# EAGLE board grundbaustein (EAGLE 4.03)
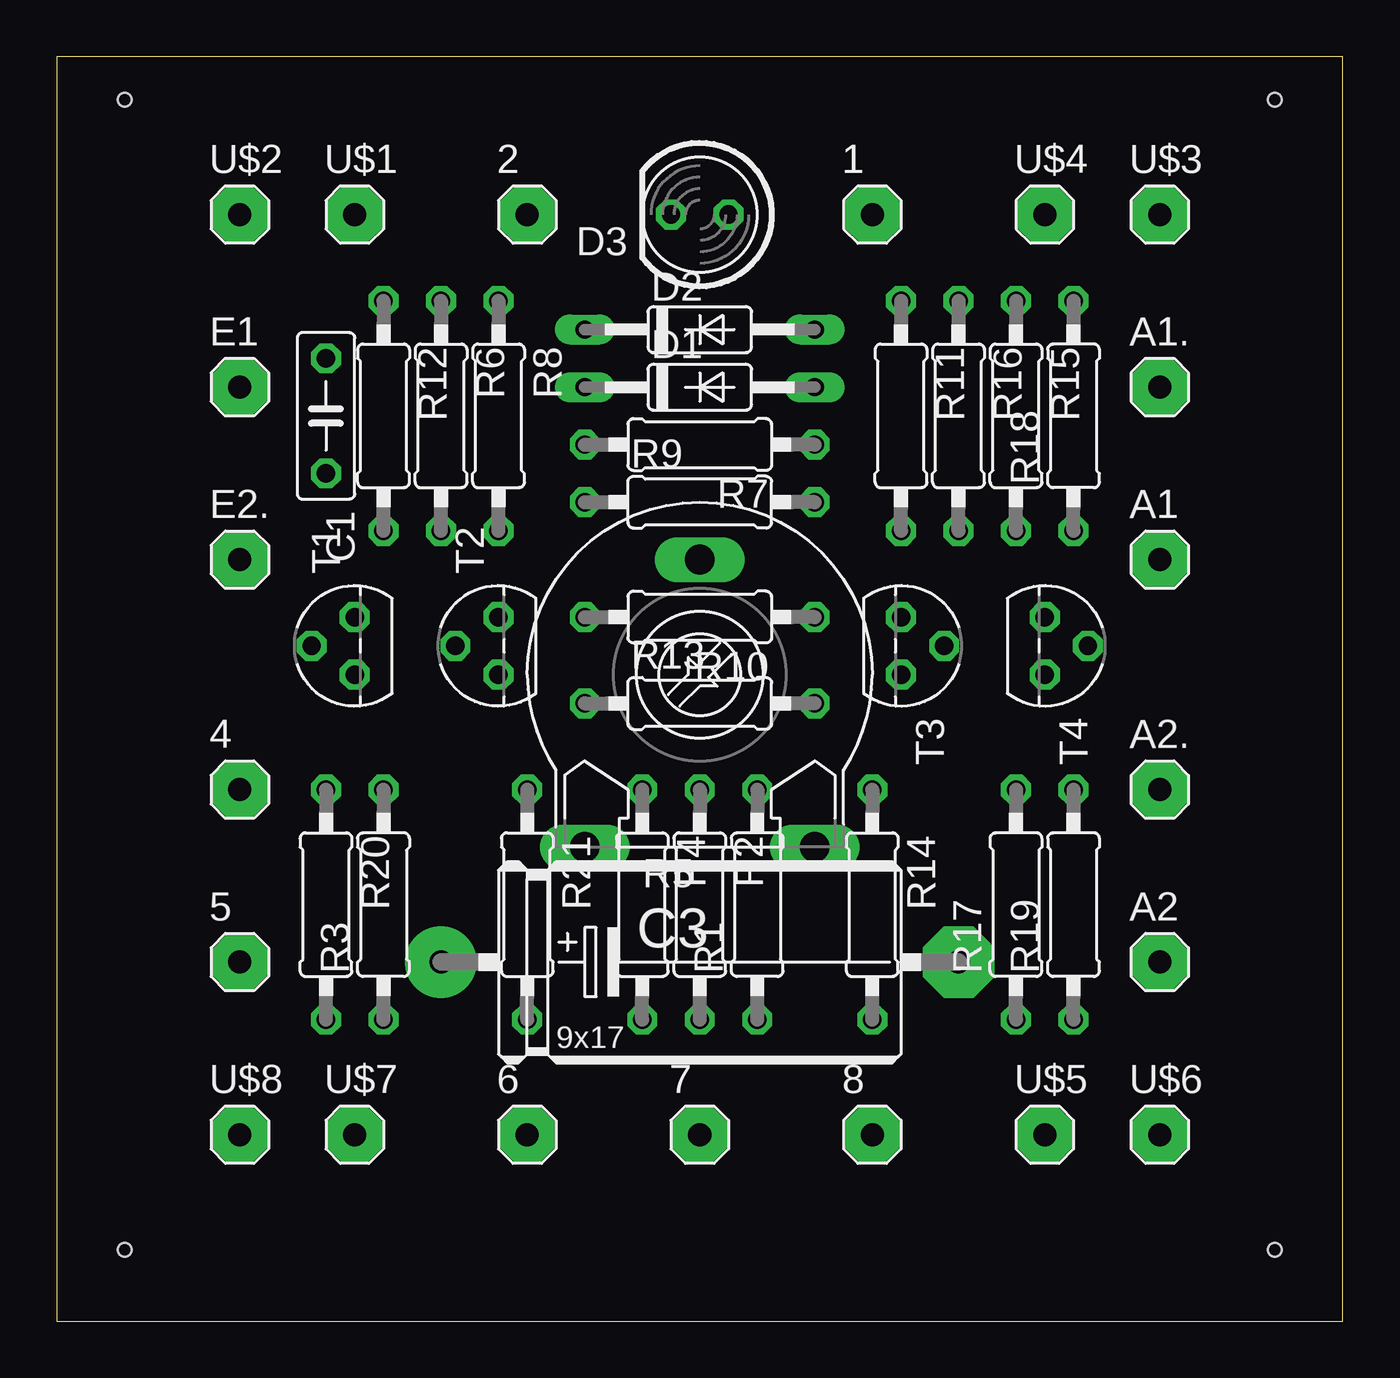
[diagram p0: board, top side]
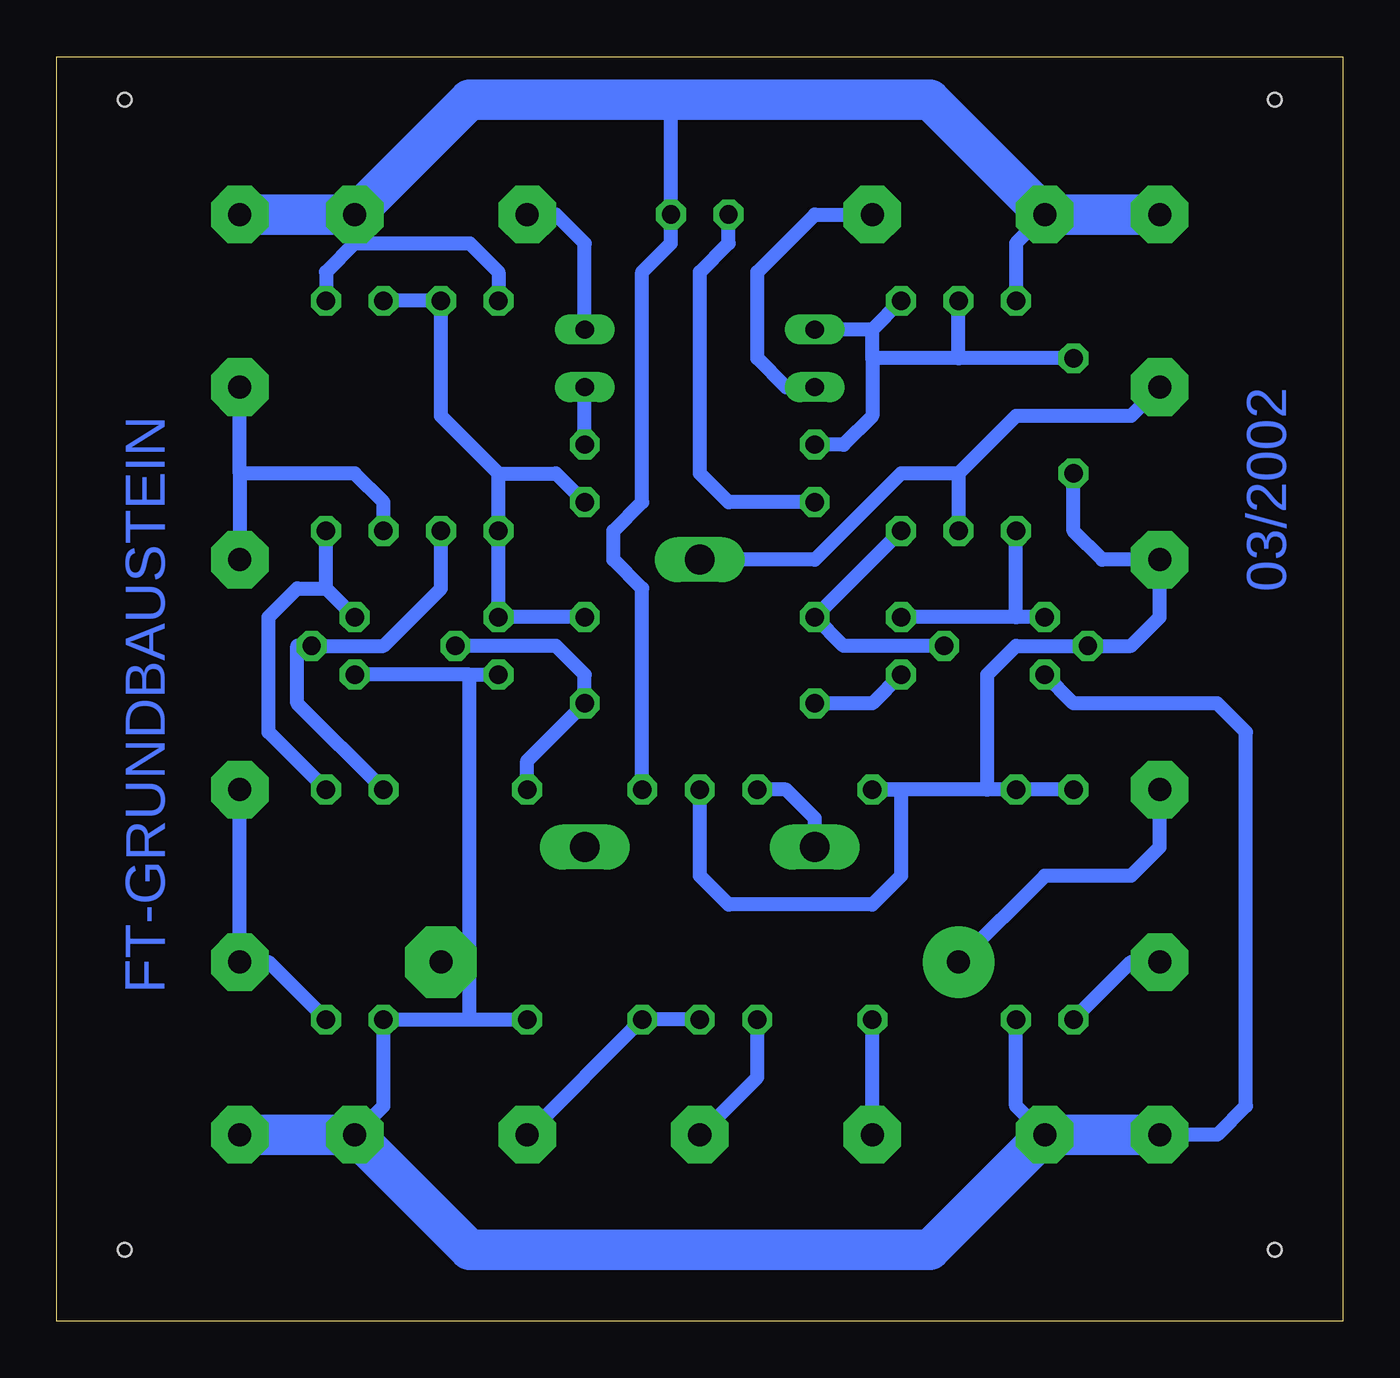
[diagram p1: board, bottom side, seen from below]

Size 56.82 x 55.87 mm. Coordinates in mm from the lower left corner, seen from the top.
Outline: 0,0 56.82,0 56.82,55.87 0,55.87 0,0
Copper layers used: Bottom
Holes 0.61 mm at 3.01,3.17 53.81,3.17 3.01,53.97 53.81,53.97

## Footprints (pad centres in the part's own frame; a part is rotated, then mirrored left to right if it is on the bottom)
1X01 = drill 1.016 pad 2.54 octagon: 1 0,0
C050-025X075 = drill 0.813 octagon: 1 -2.54,0; 2 2.54,0
E22-9 = drill 1.016 pad 3.15 round: + -11.43,0 | drill 1.016 pad 3.15 octagon: - 11.43,0
DO35-10 = drill 0.813 long: A 5.08,0; C -5.08,0
LED5MM = drill 0.813 octagon: A -1.27,0; K 1.27,0
0207/10 = drill 0.813 octagon: 1 -5.08,0; 2 5.08,0
LI15 = drill 1.321 long: 1 -5.08,-7.62; 2 0,5.08; 3 5.08,-7.62
TO92 = drill 0.813 octagon: 1 1.27,0; 2 0,1.905; 3 -1.27,0

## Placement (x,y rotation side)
1  1  [1X01]  36.03,48.89 0 top
2  2  [1X01]  20.79,48.89 0 top
4  4  [1X01]  8.09,23.49 0 top
5  PINHD-1X1-BA  [1X01]  8.09,15.87 0 top
6  PINHD-1X1-BA  [1X01]  20.79,8.25 0 top
7  7  [1X01]  28.41,8.25 0 top
8  8  [1X01]  36.03,8.25 0 top
A1  a1  [1X01]  48.73,33.65 0 top
A1.  a1  [1X01]  48.73,41.27 0 top
A2  a2  [1X01]  48.73,15.87 0 top
A2.  a2  [1X01]  48.73,23.49 0 top
C1  [C050-025X075]  11.9,40 270 top
C3  [E22-9]  28.41,15.87 0 top
D1  1N4148  [DO35-10]  28.41,41.27 0 top
D2  1N4148  [DO35-10]  28.41,43.81 0 top
D3  LED5MM  [LED5MM]  28.41,48.89 180 top
E1  e1  [1X01]  8.09,41.27 0 top
E2.  e2  [1X01]  8.09,33.65 0 top
R1  [0207/10]  30.95,18.41 90 top
R2  [0207/10]  28.41,18.41 270 top
R3  [0207/10]  14.44,18.41 90 top
R4  [0207/10]  25.87,18.41 270 top
R5  [LI15]  28.41,28.57 0 top
R6  [0207/10]  16.98,40 270 top
R7  [0207/10]  28.41,38.73 180 top
R8  [0207/10]  19.52,40 270 top
R9  [0207/10]  28.41,36.19 0 top
R10  [0207/10]  28.41,31.11 180 top
R11  [0207/10]  37.3,40 270 top
R12  [0207/10]  14.44,40 270 top
R13  [0207/10]  28.41,27.3 0 top
R14  [0207/10]  36.03,18.41 270 top
R15  [0207/10]  42.38,40 270 top
R16  [0207/10]  39.84,40 270 top
R17  [0207/10]  42.38,18.41 90 top
R18  [0207/10]  44.92,40 90 top
R19  [0207/10]  44.92,18.41 90 top
R20  [0207/10]  11.9,18.41 270 top
R21  [0207/10]  20.79,18.41 270 top
T1  BC307  [TO92]  13.17,29.84 90 top
T2  BC307  [TO92]  19.52,29.84 90 top
T3  BC238  [TO92]  37.3,29.84 270 top
T4  BC238  [TO92]  43.65,29.84 270 top
U$1  +9v  [1X01]  13.17,48.89 0 top
U$2  +9v  [1X01]  8.09,48.89 0 top
U$3  +9v  [1X01]  48.73,48.89 0 top
U$4  +9v  [1X01]  43.65,48.89 0 top
U$5  gnd  [1X01]  43.65,8.25 0 top
U$6  gnd  [1X01]  48.73,8.25 0 top
U$7  gnd  [1X01]  13.17,8.25 0 top
U$8  gnd  [1X01]  8.09,8.25 0 top

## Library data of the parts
1 2 4-8 A1 A1. A2 A2. E1 E2. U$1-U$8 = pinhead
C1 C3 R1-R4 R6-R21 = rcl
D1 D2 = diode
D3 = led
R5 = pot
T1 T2 = transistor-pnp
T3 T4 = transistor-npn

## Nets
N$1: D3.A R1.2 R11.1 R12.1 R18.2 U$1.1 U$2.1 U$3.1 U$4.1
N$2: 7.1 R4.2
N$3: 2.1 D1.C
N$4: 1.1 D2.A
N$5: 5.1 R20.2
N$6: 4.1 C3.+
N$7: 6.1 R21.2
N$9: D1.A R7.1
N$10: R4.1 R5.1
N$11: 8.1 R1.1 R2.2
N$12: D3.K R9.1
N$13: E1.1 R5.2 R6.2
N$14: R16.2 R17.2 T4.2
N$15: C1.1 D2.C R6.1 R7.2 R8.1
N$16: R9.2 R10.1 R11.2 R15.1 R16.1 T3.3
N$17: R8.2 R10.2 T2.2
N$19: C1.2 E2..1 R2.1 R3.2 R20.1 R21.1 T1.2
N$20: C3.- R3.1 R14.2 R17.1 T1.3 T3.1 T4.1 U$5.1 U$6.1 U$7.1 U$8.1
N$24: R12.2 T1.1 T2.1
N$25: R13.1 T2.3
N$26: R13.2 R14.1 T3.2
N$38: R18.1 R19.2 T4.3
N$43: A2.1 A2..1 R19.1
N$45: A1.1 A1..1 R15.2

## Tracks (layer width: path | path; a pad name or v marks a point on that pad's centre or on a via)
N$1
  Bottom 0.61: U$4.1 43.65,47.62 | 43.65,47.62 44.92,46.35 R18.2 | R11.1 37.3,46.35 38.57,47.62 43.65,47.62 | 29.68,53.97 D3.A 29.68,47.62 30.95,46.35 30.95,36.19 32.22,34.92 32.22,33.65 30.95,32.38 R1.2 | U$1.1 14.44,47.62 R12.1
  Bottom 1.778: U$2.1 U$1.1 18.25,53.97 29.68,53.97 38.57,53.97 U$4.1 U$3.1
N$2
  Bottom 0.61: R4.2 25.87,10.79 7.1
N$3
  Bottom 0.61: 2.1 23.33,48.89 25.87,46.35 25.87,42.54 24.6,41.27 D1.C
N$4
  Bottom 0.61: 1.1 34.76,48.89 33.49,47.62 D2.A
N$5
  Bottom 0.61: 5.1 9.36,15.87 R20.2
N$6
  Bottom 0.61: 4.1 8.09,20.95 9.36,19.68 13.17,19.68 C3.+
N$7
  Bottom 0.61: 6.1 R21.2
N$9
  Bottom 0.61: R7.1 D1.A
N$10
  Bottom 0.61: R4.1 24.6,23.49 23.33,22.22 R5.1
N$11
  Bottom 0.61: R2.2 R1.1 8.1
N$12
  Bottom 0.61: R9.1 27.14,36.19 28.41,37.46 28.41,46.35 27.14,47.62 D3.K
N$13
  Bottom 0.61: E1.1 9.36,40 14.44,40 16.98,37.46 | 16.98,37.46 R6.2 | R5.2 23.33,33.65 19.52,37.46 16.98,37.46
N$14
  Bottom 0.61: R16.2 39.84,32.38 42.38,29.84 T4.2 46.19,29.84 46.19,27.3 R17.2
N$15
  Bottom 0.61: R7.2 22.06,38.73 20.79,40 20.79,42.54 | 20.79,42.54 20.79,43.81 | 20.79,43.81 D2.C | C1.1 16.98,42.54 | 16.98,42.54 20.79,42.54 | 16.98,42.54 R6.1 | 20.79,43.81 R8.1
N$16
  Bottom 0.61: 37.3,37.46 R11.2 T3.3 R10.1 | 37.3,37.46 39.84,40 R16.1 R15.1 | 37.3,37.46 34.76,37.46 R9.2
N$17
  Bottom 0.61: T2.2 22.06,29.84 R10.2 R8.2
N$19
  Bottom 0.61: R2.1 28.41,19.68 27.14,18.41 20.79,18.41 19.52,19.68 19.52,23.49 R21.1 R3.2 | R20.1 R3.2 | R3.2 15.71,23.49 15.71,28.57 14.44,29.84 T1.2 9.36,29.84 8.09,31.11 E2..1 10.63,33.65 11.9,34.92 C1.2
N$20
  Bottom 0.61: 38.57,28.57 T4.1 | 38.57,28.57 T3.1 | U$5.1 42.38,9.52 R17.1 38.57,13.33 | R3.1 14.44,9.52 U$7.1 | T1.3 11.9,27.3 5.55,27.3 4.28,26.03 4.28,9.52 5.55,8.25 U$8.1 | 38.57,15.87 38.57,28.57 | 38.57,13.33 R14.2 | 38.57,13.33 38.57,15.87 | 38.57,15.87 C3.-
  Bottom 1.778: U$8.1 U$7.1 18.25,3.17 38.57,3.17 U$5.1 U$6.1
N$24
  Bottom 0.61: 14.44,31.11 T2.1 | T1.1 14.44,31.11 | 14.44,31.11 R12.2
N$25
  Bottom 0.61: R13.1 20.79,27.3 T2.3
N$26
  Bottom 0.61: T3.2 34.76,29.84 33.49,28.57 R13.2 36.03,24.76 R14.1
N$38
  Bottom 0.61: 44.92,32.38 R18.1 | 44.92,32.38 46.19,32.38 47.46,31.11 47.46,26.03 R19.2 | 44.92,32.38 T4.3
N$43
  Bottom 0.61: R19.1 47.46,15.87 A2.1 A2..1
N$45
  Bottom 0.61: 48.73,37.46 A1..1 | 48.73,37.46 A1.1 | R15.2 42.38,36.19 43.65,37.46 48.73,37.46

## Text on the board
Bottom: 03/2002 | FT-GRUNDBAUSTEIN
